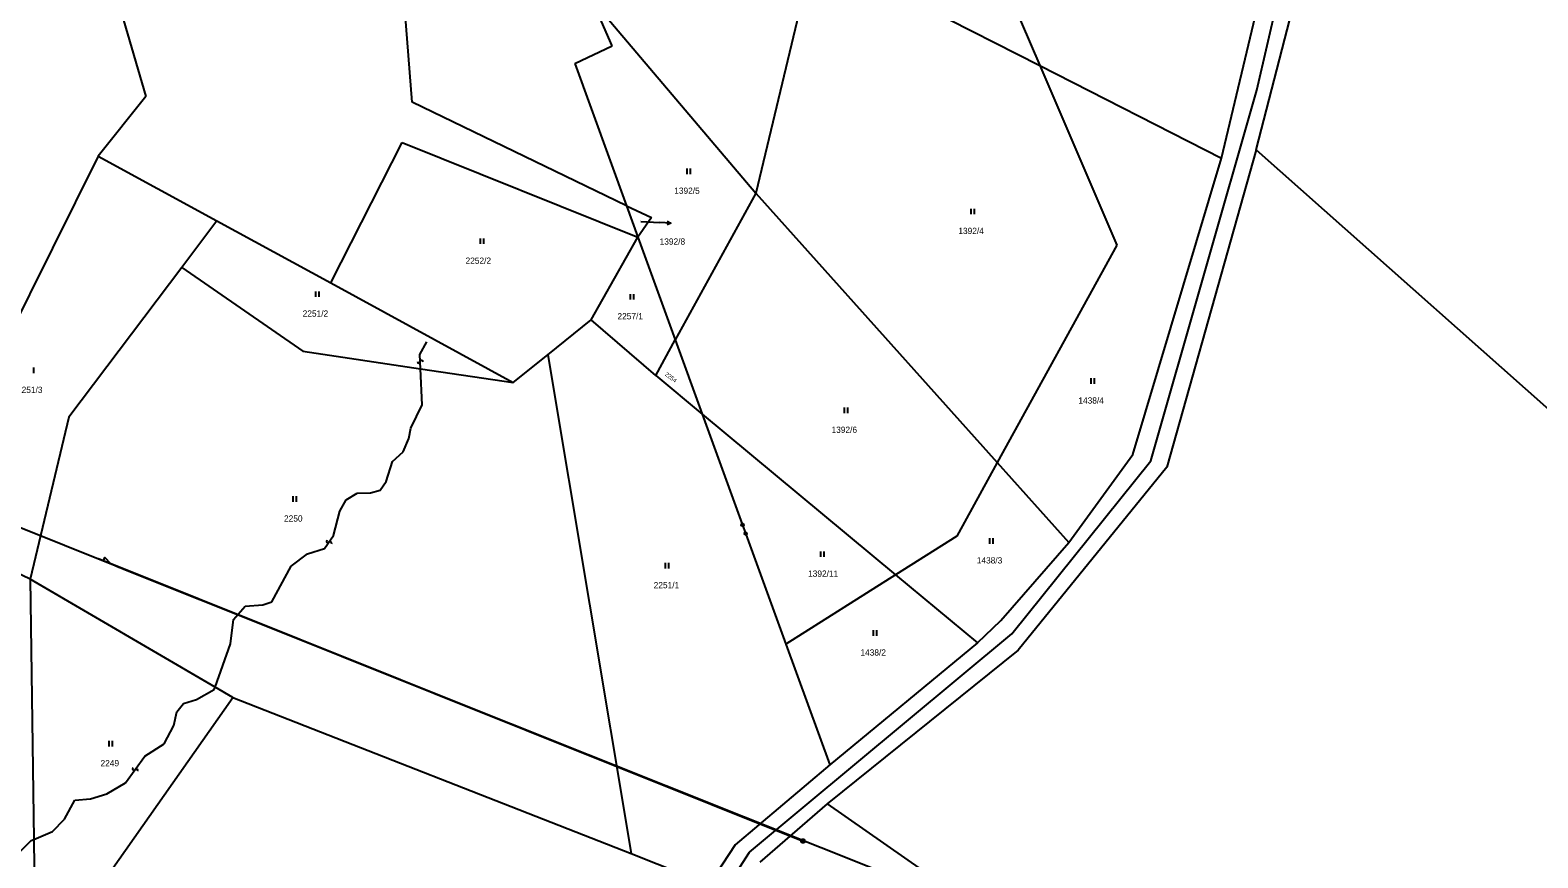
# Model space of a CAD drawing. Extents: x -747792 to -745414, y -1093712 to -1091463.
# Drawn here: x -746371.5 to -746166, y -1092533.3 to -1092420.5 of the extents above; entities that cross this region are included whole.
import ezdxf

# ---------------------------------------------------------------- set-up
doc = ezdxf.new("R2010")
doc.units = 0
for name, color, linetype in [('Pracovní_bod JDTM STC_VC', 7, 'Continuous'), ('Pracovní_bod JDTM STC_VC - číslo', 7, 'Continuous'), ('Pracovní_bod NN - výška', 7, 'Continuous'), ('Pracovní_bod polohopisu', 7, 'Continuous'), ('Pracovní_bod polohopisu - výška', 7, 'Continuous'), ('Pracovní_bod polohopisu - číslo', 7, 'Continuous')]:
    doc.layers.add(name, color=color, linetype=linetype)

msp = doc.modelspace()

# ---------------------------------------------------------------- linework, layer by layer
at = {"layer": 'Pracovní_bod JDTM STC_VC - číslo'}
for points in [[(-746281.97, -1092439.33), (-746281.97, -1092440.08)], [(-746281.47, -1092440.08), (-746281.47, -1092439.33)], [(-746243.25, -1092444.81), (-746243.25, -1092445.56)], [(-746242.75, -1092445.56), (-746242.75, -1092444.81)], [(-746310.18, -1092448.87), (-746310.18, -1092449.62)], [(-746309.68, -1092449.62), (-746309.68, -1092448.87)], [(-746332.6, -1092456.08), (-746332.6, -1092456.83)], [(-746332.1, -1092456.83), (-746332.1, -1092456.08)], [(-746289.74, -1092456.45), (-746289.74, -1092457.2)], [(-746289.24, -1092457.2), (-746289.24, -1092456.45)], [(-746371.04, -1092467.23), (-746371.04, -1092466.48)], [(-746226.92, -1092467.93), (-746226.92, -1092468.68)], [(-746226.42, -1092468.68), (-746226.42, -1092467.93)], [(-746260.54, -1092471.92), (-746260.54, -1092472.67)], [(-746260.04, -1092472.67), (-746260.04, -1092471.92)], [(-746335.73, -1092484.02), (-746335.73, -1092484.77)], [(-746335.23, -1092484.77), (-746335.23, -1092484.02)], [(-746240.72, -1092489.73), (-746240.72, -1092490.48)], [(-746240.22, -1092490.48), (-746240.22, -1092489.73)], [(-746263.75, -1092491.54), (-746263.75, -1092492.29)], [(-746263.25, -1092492.29), (-746263.25, -1092491.54)], [(-746284.95, -1092493.11), (-746284.95, -1092493.86)], [(-746284.45, -1092493.86), (-746284.45, -1092493.11)], [(-746256.59, -1092502.29), (-746256.59, -1092503.04)], [(-746256.09, -1092503.04), (-746256.09, -1092502.29)], [(-746360.78, -1092517.38), (-746360.78, -1092518.13)], [(-746360.28, -1092518.13), (-746360.28, -1092517.38)]]:
    msp.add_lwpolyline(points, dxfattribs=at)
at = {"layer": 'Pracovní_bod NN - výška'}
for points in [[(-746254.89, -1092376.39), (-746233.88, -1092425.29)], [(-746319.46, -1092430.3), (-746322.58, -1092390.35)], [(-746264.66, -1092409.59), (-746272.58, -1092442.68)], [(-746264.66, -1092409.59), (-746233.88, -1092425.29)], [(-746361.32, -1092410.5), (-746355.77, -1092429.53)], [(-746209.09, -1092437.94), (-746203.8, -1092415.74)], [(-746292.19, -1092422.6), (-746294.88, -1092416.36)], [(-746294.88, -1092416.36), (-746272.58, -1092442.68)], [(-746292.19, -1092422.6), (-746294.88, -1092416.36)], [(-746204.38, -1092436.79), (-746199.41, -1092417.6)], [(-746204.28, -1092428.66), (-746201.46, -1092416.48)], [(-746297.28, -1092425.01), (-746292.19, -1092422.6)], [(-746297.28, -1092425.01), (-746292.19, -1092422.6)], [(-746297.28, -1092425.01), (-746290.23, -1092444.4)], [(-746297.28, -1092425.01), (-746290.23, -1092444.4)], [(-746233.88, -1092425.29), (-746209.09, -1092437.94)], [(-746233.88, -1092425.29), (-746223.37, -1092449.76)], [(-746355.77, -1092429.53), (-746362.25, -1092437.65)], [(-746290.23, -1092444.4), (-746319.46, -1092430.3)], [(-746218.73, -1092479.2), (-746204.28, -1092428.66)], [(-746330.52, -1092454.93), (-746320.79, -1092435.79)], [(-746320.79, -1092435.79), (-746288.66, -1092448.71)], [(-746362.25, -1092437.65), (-746387.21, -1092487.8)], [(-746362.25, -1092437.65), (-746346.08, -1092446.46)], [(-746221.18, -1092478.34), (-746209.09, -1092437.94)], [(-746204.38, -1092436.79), (-746216.56, -1092480.03)], [(-746204.38, -1092436.79), (-746155.58, -1092480.03)], [(-746272.58, -1092442.68), (-746283.57, -1092462.69)], [(-746272.58, -1092442.68), (-746239.68, -1092479.43)], [(-746290.23, -1092444.4), (-746288.66, -1092448.71)], [(-746290.23, -1092444.4), (-746286.8, -1092446.02)], [(-746290.23, -1092444.4), (-746288.66, -1092448.71)], [(-746346.08, -1092446.46), (-746350.86, -1092452.81)], [(-746346.08, -1092446.46), (-746330.52, -1092454.93)], [(-746286.8, -1092446.02), (-746288.66, -1092448.71)], [(-746295.05, -1092459.98), (-746288.66, -1092448.71)], [(-746288.66, -1092448.71), (-746283.57, -1092462.69)], [(-746288.66, -1092448.71), (-746283.57, -1092462.69)], [(-746223.37, -1092449.76), (-746239.68, -1092479.43)], [(-746350.86, -1092452.81), (-746366.23, -1092473.23)], [(-746350.86, -1092452.81), (-746334.33, -1092464.24)], [(-746330.52, -1092454.93), (-746305.67, -1092468.51)], [(-746300.96, -1092464.73), (-746295.05, -1092459.98)], [(-746286.24, -1092467.54), (-746295.05, -1092459.98)], [(-746286.24, -1092467.54), (-746283.57, -1092462.69)], [(-746283.57, -1092462.69), (-746279.89, -1092472.82)], [(-746283.57, -1092462.69), (-746279.89, -1092472.82)], [(-746334.33, -1092464.24), (-746318.3, -1092466.63)], [(-746305.67, -1092468.51), (-746300.96, -1092464.73)], [(-746300.96, -1092464.73), (-746289.6, -1092532.73)], [(-746318.3, -1092466.63), (-746305.67, -1092468.51)], [(-746286.24, -1092467.54), (-746279.89, -1092472.82)], [(-746366.23, -1092473.23), (-746371.51, -1092495.32)], [(-746279.89, -1092472.82), (-746268.49, -1092504.16)], [(-746279.89, -1092472.82), (-746253.52, -1092494.72)], [(-746279.89, -1092472.82), (-746268.49, -1092504.16)], [(-746239.68, -1092479.43), (-746245.19, -1092489.47)], [(-746239.68, -1092479.43), (-746229.93, -1092490.32)], [(-746237.69, -1092502.76), (-746218.73, -1092479.2)], [(-746229.93, -1092490.32), (-746221.18, -1092478.34)], [(-746216.56, -1092480.03), (-746236.82, -1092504.99)], [(-746371.51, -1092495.32), (-746387.21, -1092487.8)], [(-746274.22, -1092487.93), (-746274.28, -1092488.05), (-746274.41, -1092488.1), (-746274.53, -1092488.04), (-746274.57, -1092487.92), (-746274.52, -1092487.8), (-746274.39, -1092487.75), (-746274.27, -1092487.81), (-746274.22, -1092487.93), (-746274.24, -1092487.93), (-746274.28, -1092487.82), (-746274.34, -1092487.8), (-746274.27, -1092487.99), (-746274.29, -1092488.04), (-746274.39, -1092487.77), (-746274.42, -1092487.79), (-746274.33, -1092488.05), (-746274.37, -1092488.06), (-746274.46, -1092487.8), (-746274.5, -1092487.82), (-746274.4, -1092488.08), (-746274.45, -1092488.05), (-746274.52, -1092487.87), (-746274.55, -1092487.92), (-746274.51, -1092488.03)], [(-746274.22, -1092487.93), (-746274.28, -1092488.05), (-746274.41, -1092488.1), (-746274.53, -1092488.04), (-746274.57, -1092487.92), (-746274.52, -1092487.8), (-746274.39, -1092487.75), (-746274.27, -1092487.81), (-746274.22, -1092487.93), (-746274.24, -1092487.93), (-746274.28, -1092487.82), (-746274.34, -1092487.8), (-746274.27, -1092487.99), (-746274.29, -1092488.04), (-746274.39, -1092487.77), (-746274.42, -1092487.79), (-746274.33, -1092488.05), (-746274.37, -1092488.06), (-746274.46, -1092487.8), (-746274.5, -1092487.82), (-746274.4, -1092488.08), (-746274.45, -1092488.05), (-746274.52, -1092487.87), (-746274.55, -1092487.92), (-746274.51, -1092488.03)], [(-746273.8, -1092489.11), (-746273.85, -1092489.23), (-746273.98, -1092489.28), (-746274.1, -1092489.22), (-746274.15, -1092489.09), (-746274.09, -1092488.97), (-746273.96, -1092488.92), (-746273.84, -1092488.98), (-746273.8, -1092489.11), (-746273.82, -1092489.1), (-746273.86, -1092488.99), (-746273.91, -1092488.96), (-746273.84, -1092489.15), (-746273.87, -1092489.2), (-746273.96, -1092488.94), (-746274, -1092488.95), (-746273.9, -1092489.22), (-746273.94, -1092489.23), (-746274.04, -1092488.97), (-746274.08, -1092488.98), (-746273.98, -1092489.24), (-746274.03, -1092489.22), (-746274.1, -1092489.03), (-746274.12, -1092489.08), (-746274.08, -1092489.2)], [(-746273.8, -1092489.11), (-746273.85, -1092489.23), (-746273.98, -1092489.28), (-746274.1, -1092489.22), (-746274.15, -1092489.09), (-746274.09, -1092488.97), (-746273.96, -1092488.92), (-746273.84, -1092488.98), (-746273.8, -1092489.11), (-746273.82, -1092489.1), (-746273.86, -1092488.99), (-746273.91, -1092488.96), (-746273.84, -1092489.15), (-746273.87, -1092489.2), (-746273.96, -1092488.94), (-746274, -1092488.95), (-746273.9, -1092489.22), (-746273.94, -1092489.23), (-746274.04, -1092488.97), (-746274.08, -1092488.98), (-746273.98, -1092489.24), (-746274.03, -1092489.22), (-746274.1, -1092489.03), (-746274.12, -1092489.08), (-746274.08, -1092489.2)], [(-746245.19, -1092489.47), (-746253.52, -1092494.72)], [(-746239.19, -1092500.97), (-746229.93, -1092490.32)], [(-746346.32, -1092510.03), (-746371.51, -1092495.32)], [(-746371.51, -1092495.32), (-746371.03, -1092530.81)], [(-746253.52, -1092494.72), (-746268.49, -1092504.16)], [(-746253.52, -1092494.72), (-746242.37, -1092503.98)], [(-746242.37, -1092503.98), (-746239.19, -1092500.97)], [(-746273.45, -1092532.54), (-746237.69, -1092502.76)], [(-746268.49, -1092504.16), (-746262.5, -1092520.63)], [(-746268.49, -1092504.16), (-746262.5, -1092520.63)], [(-746242.37, -1092503.98), (-746262.5, -1092520.63)], [(-746236.82, -1092504.99), (-746262.85, -1092525.95)], [(-746343.87, -1092511.46), (-746346.32, -1092510.03)], [(-746370.78, -1092549.7), (-746343.87, -1092511.46)], [(-746343.87, -1092511.46), (-746289.6, -1092532.73)], [(-746262.5, -1092520.63), (-746275.41, -1092531.52)], [(-746262.5, -1092520.63), (-746275.41, -1092531.52)], [(-746262.85, -1092525.95), (-746272.06, -1092533.9)], [(-746262.85, -1092525.95), (-746092.21, -1092645.1)], [(-746371.03, -1092530.81), (-746370.78, -1092549.7)], [(-746289.6, -1092532.73), (-746278.93, -1092536.93)], [(-746282.01, -1092545.8), (-746273.45, -1092532.54)], [(-746275.41, -1092531.52), (-746278.93, -1092536.93)], [(-746275.41, -1092531.52), (-746278.93, -1092536.93)]]:
    msp.add_lwpolyline(points, dxfattribs=at)
at = {"layer": 'Pracovní_bod polohopisu'}
for points in [[(-746318.4, -1092464.7), (-746317.42, -1092462.97)], [(-746318.73, -1092465.66), (-746318.67, -1092465.81), (-746318.51, -1092465.86), (-746318.38, -1092465.78), (-746318.31, -1092465.54), (-746318.17, -1092465.47), (-746318.02, -1092465.53), (-746317.97, -1092465.67)], [(-746318.3, -1092466.63), (-746318.4, -1092464.7)], [(-746318.06, -1092471.53), (-746318.3, -1092466.63)], [(-746319.62, -1092474.74), (-746318.06, -1092471.53)], [(-746319.91, -1092476.15), (-746319.62, -1092474.74)], [(-746320.66, -1092477.94), (-746319.91, -1092476.15)], [(-746323, -1092482), (-746322.12, -1092479.27)], [(-746322.12, -1092479.27), (-746320.66, -1092477.94)], [(-746328.44, -1092484.52), (-746326.95, -1092483.61)], [(-746326.95, -1092483.61), (-746325.14, -1092483.57)], [(-746325.14, -1092483.57), (-746323.82, -1092483.17)], [(-746323.82, -1092483.17), (-746323, -1092482)], [(-746329.28, -1092486.06), (-746328.44, -1092484.52)], [(-746330.18, -1092489.38), (-746329.28, -1092486.06)], [(-746331.41, -1092491.14), (-746330.18, -1092489.38)], [(-746331.09, -1092490.02), (-746331.13, -1092490.18), (-746331.04, -1092490.31), (-746330.89, -1092490.33), (-746330.68, -1092490.19), (-746330.53, -1092490.22), (-746330.45, -1092490.36), (-746330.5, -1092490.5)], [(-746335.96, -1092493.55), (-746333.69, -1092491.85)], [(-746333.69, -1092491.85), (-746331.41, -1092491.14)], [(-746338.59, -1092498.42), (-746335.96, -1092493.55)], [(-746343.8, -1092500.84), (-746342.22, -1092499)], [(-746342.22, -1092499), (-746339.81, -1092498.81)], [(-746339.81, -1092498.81), (-746338.59, -1092498.42)], [(-746344.19, -1092504.15), (-746343.8, -1092500.84)], [(-746346.32, -1092510.03), (-746344.19, -1092504.15)], [(-746348.83, -1092511.74), (-746346.44, -1092510.38)], [(-746346.44, -1092510.38), (-746346.32, -1092510.03)], [(-746351.54, -1092513.39), (-746350.63, -1092512.25)], [(-746350.63, -1092512.25), (-746348.83, -1092511.74)], [(-746351.93, -1092515.28), (-746351.54, -1092513.39)], [(-746353.24, -1092517.79), (-746351.93, -1092515.28)], [(-746355.9, -1092519.44), (-746353.24, -1092517.79)], [(-746358.52, -1092523.1), (-746355.9, -1092519.44)], [(-746357.5, -1092521.03), (-746357.55, -1092521.18), (-746357.46, -1092521.32), (-746357.31, -1092521.34), (-746357.1, -1092521.2), (-746356.95, -1092521.23), (-746356.87, -1092521.37), (-746356.92, -1092521.51)], [(-746363.31, -1092525.26), (-746361.09, -1092524.61)], [(-746361.09, -1092524.61), (-746358.52, -1092523.1)], [(-746366.84, -1092528.06), (-746365.45, -1092525.43)], [(-746365.45, -1092525.43), (-746363.31, -1092525.26)], [(-746368.48, -1092529.73), (-746366.84, -1092528.06)], [(-746375.8, -1092535.36), (-746371.38, -1092530.96)], [(-746371.38, -1092530.96), (-746371.03, -1092530.81)], [(-746371.03, -1092530.81), (-746368.48, -1092529.73)]]:
    msp.add_lwpolyline(points, dxfattribs=at)
at = {"layer": 'Pracovní_bod polohopisu - výška'}
for points in [[(-746288.27, -1092446.56), (-746285.68, -1092446.69)], [(-746284.18, -1092446.77), (-746285.68, -1092446.69)], [(-746284.67, -1092446.49), (-746284.18, -1092446.77), (-746284.69, -1092446.99)]]:
    msp.add_lwpolyline(points, dxfattribs=at)
at = {"layer": 'Pracovní_bod polohopisu - číslo'}
for points in [[(-746455.03, -1092455.38), (-746266.15, -1092531.03), (-746362.22, -1092492.55)], [(-746361.98, -1092492.65), (-746361.52, -1092492.83), (-746361.33, -1092492.37), (-746360.59, -1092493.2), (-746359.2, -1092493.76)], [(-746358.97, -1092493.85), (-746147.44, -1092578.31), (-746254.83, -1092535.43)], [(-746266.23, -1092530.79), (-746266.07, -1092530.79), (-746265.95, -1092530.88), (-746265.9, -1092531.02), (-746265.95, -1092531.17), (-746266.07, -1092531.26), (-746266.23, -1092531.26), (-746266.35, -1092531.17), (-746266.4, -1092531.02), (-746266.35, -1092530.88), (-746266.23, -1092530.79), (-746266.21, -1092530.81), (-746266.09, -1092530.81), (-746266.01, -1092530.85), (-746266.29, -1092530.85), (-746266.33, -1092530.89), (-746265.97, -1092530.89), (-746265.97, -1092530.93), (-746266.33, -1092530.93), (-746266.35, -1092530.97), (-746265.95, -1092530.97), (-746265.93, -1092531.01), (-746266.37, -1092531.01), (-746266.37, -1092531.05), (-746265.93, -1092531.05), (-746265.95, -1092531.09), (-746266.35, -1092531.09), (-746266.34, -1092531.13), (-746265.94, -1092531.13), (-746265.97, -1092531.17), (-746266.33, -1092531.17), (-746266.29, -1092531.21), (-746266.01, -1092531.21), (-746266.06, -1092531.25), (-746266.23, -1092531.25)]]:
    msp.add_lwpolyline(points, dxfattribs=at)

# ---------------------------------------------------------------- texts
at = {"layer": 'Pracovní_bod JDTM STC_VC'}
for s, p in [('1392/5', (-746283.71, -1092442.78)), ('1392/4', (-746244.97, -1092448.26)), ('2252/2', (-746312.16, -1092452.32)), ('2251/2', (-746334.37, -1092459.53)), ('2257/1', (-746291.45, -1092459.9)), ('2251/3', (-746373.32, -1092469.93)), ('1438/4', (-746228.61, -1092471.38)), ('1392/6', (-746262.26, -1092475.37)), ('2250', (-746336.91, -1092487.47)), ('1392/11', (-746265.46, -1092494.99)), ('1438/3', (-746242.46, -1092493.18)), ('2251/1', (-746286.51, -1092496.56)), ('1438/2', (-746258.32, -1092505.74)), ('2249', (-746361.93, -1092520.83))]:
    msp.add_text(s, height=0.85, dxfattribs=at).set_placement(p)
for s, height, rotation, p in [('1392/8', 0.05, 295.3597, (-746288.32, -1092446.45)), ('2254', 0.57, 323.0909, (-746285.03, -1092467.51))]:
    msp.add_text(s, height=height, rotation=rotation, dxfattribs=at).set_placement(p)
at = {"layer": 'Pracovní_bod polohopisu - výška'}
msp.add_text('1392/8', height=0.85, dxfattribs=at).set_placement((-746285.7, -1092449.71))

doc.saveas('drawing.dxf')
